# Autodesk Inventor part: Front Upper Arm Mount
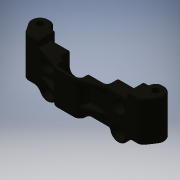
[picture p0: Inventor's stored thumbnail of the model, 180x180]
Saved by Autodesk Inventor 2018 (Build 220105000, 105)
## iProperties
Shininess: 41.0
Compacted: True
Length Units: 11272
Angle Units: 11279
Time Units: 11290
Mass Units: 11286
Length Display Precision: 3
Angle Display Precision: 2
Company: Autodesk
Created: 2001-02
Part Number: Front Upper Arm Mount
Document SubType Name: Modeling
Designer: Autodesk, Inc.
Material: Stiffzel
Project: Inventor Samples
Density: 1.28 g/cm^3
Mass: 8.2438 g
Surface Area: 43.7502 cm^2
Volume: 6.44047 cm^3
Appearance: Stiffzel
Density: 0.0
Volumn: 0.0
Area: 0.0
PropertySet Name: Model Information
Control State: 0
Master: False
Checked Out: False
Author: Autodesk, Inc.
Revision Number: A
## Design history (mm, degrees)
sketch "Sketch1"
  geometry: L1 (20.137, 81.089)-(30.678, 81.089); L2 (30.678, 81.089)-(30.678, 100.139); L3 (30.678, 100.139)-(20.137, 100.139); L4 (20.137, 100.139)-(20.137, 81.089); L5 (-21.011, 81.089)-(-31.552, 81.089); L6 (-31.552, 81.089)-(-31.552, 100.139); L7 (-31.552, 100.139)-(-21.011, 100.139); L8 (-21.011, 100.139)-(-21.011, 81.089)
  constraints: 16 end point, 4 parallel, 3 collinear, 2 horizontal, 2 perpendicular
  dimensions: "d0" = 41.148 distance between parallel lines of L4 L8; "d1" = 10.541 distance of L2.end L3.end; "d2" = 19.05 distance of L1.end L2.end
extrude "Extrusion1" new body sketch "Sketch1" distance "d3" = 8.001; taper "d4" = 0 deg
sketch "Sketch15"
  geometry: L1 (21.011, 81.089)-(31.552, 81.089) reference; L2 (31.552, 100.139)-(23.551, 100.139); L3 (23.551, 100.139)-(23.551, 81.089); L4 (23.551, 81.089)-(31.552, 81.089); L5 (31.552, 81.089)-(31.552, 100.139); L6 (-30.678, 81.089)-(-30.678, 100.139) reference; L7 (-30.678, 100.139)-(-20.137, 100.139) reference; L8 (-30.678, 81.089)-(-20.137, 81.089) reference; L9 (-22.677, 100.139)-(-22.677, 81.089)
  constraints: 10 end point, 3 point on line, 2 parallel, 2 perpendicular, 1 horizontal
  dimensions: "d81" = 8.001 distance between parallel lines of L5 L3 (= d3); "d82" = 8.001 distance between parallel lines of L9 L6 (= d3)
extrude "Extrusion12" join sketch "Sketch15" distance "d83" = 3.175; taper "d84" = 0 deg
fillet "Fillet1" dims "d5" = 4.0005 (= 0.5 x d3)
sketch "Sketch16"
  geometry: L1 (0, 0)-(0, 7.176) reference; L2 (0, 0)-(10.541, 0) reference; L3 (8.001, 11.176)-(4.001, 11.176) reference; L4 (62.23, 7.176)-(62.23, 0) reference; L5 (51.689, 0)-(62.23, 0) reference; L6 (0.679, 4.945)-(4.001, 0); L7 (61.551, 4.945)-(58.229, 0); A1 r 4.001 centre (4.001, 7.176) between (4.001, 11.176) and (0, 7.176) reference; A2 r 4.001 centre (58.229, 7.176) between (62.23, 7.176) and (58.229, 11.176) reference; A3 r 4.001 centre (58.229, 7.176) between (61.551, 4.945) and (62.23, 7.176); A4 r 4.001 centre (4.001, 7.176) between (4.001, 11.176) and (0.679, 4.945); 1 further point
  constraints: 6 point on circle, 5 end point, 3 coincident, 2 centre point, 2 point on line, 2 tangent, 2 vertical alignment
extrude "Extrusion13" cut sketch "Sketch16" extent not by distance; stored distance "d85" = 2.54; taper "d86" = 0 deg
sketch "Sketch2"
  geometry: L1 (-21.011, 100.139)-(-21.011, 81.089) reference; L2 (20.137, 81.089)-(20.137, 100.139) reference; L3 (20.137, 81.089)-(-21.011, 81.089); L4 (-21.011, 81.089)-(-21.011, 97.281); L5 (-21.011, 97.281)-(20.137, 97.281); L6 (20.137, 97.281)-(20.137, 81.089)
  constraints: 8 end point, 2 parallel, 1 horizontal, 1 perpendicular, 1 point on line
  dimensions: "d6" = 16.1925 distance between parallel lines of L3 L5
extrude "Extrusion2" join sketch "Sketch2" distance "d7" = 6.35; taper "d8" = 0 deg
sketch "Sketch3"
  geometry: L1 (20.137, 97.281)-(20.137, 100.139) reference; L2 (-21.011, 100.139)-(-21.011, 97.281) reference; L3 (26.677, 81.089)-(-27.552, 81.089) reference; C1 r 4.001 at (16.136, 81.089); C2 r 4.001 at (-17.011, 81.089)
  constraints: 2 centre point, 2 point on line, 2 tangent, 1 equal radius
  dimensions: "d9" = 8.001 diameter of C1
extrude "Extrusion3" join sketch "Sketch3" distance "d10" = 6.35 (= d7); taper "d11" = 0 deg
fillet "Fillet2" dims "d12" = 3.175
sketch "Sketch4"
  geometry: L1 (41.148, 6.35)-(0, 6.35) reference; L2 (41.148, 0)-(0, 0) reference; L3 (41.148, 6.35)-(41.148, 0) reference; L4 (23.559, 0)-(23.559, -1.016); L5 (20.384, -4.191)-(12.764, -4.191); L6 (9.589, -1.016)-(9.588, 0); L7 (8.001, 0)-(8.001, 6.35) reference; A1 r 3.175 centre (20.384, -1.016) between (20.384, -4.191) and (23.559, -1.016); A2 r 3.175 centre (12.764, -1.016) between (9.589, -1.016) and (12.764, -4.191)
  constraints: 6 end point, 4 point on circle, 4 tangent, 2 centre point, 2 perpendicular, 2 point on line, 1 equal radius, 1 parallel
  dimensions: "d13" = 3.175 radius of A1; "d14" = 10.541 distance between parallel lines of L1 L5; "d15" = 13.97 distance between parallel lines of L6 L4; "d17" = 1.5875 distance between parallel lines of L7 L6
extrude "Extrusion4" join sketch "Sketch4" stored distance "d18" = 25.4; taper "d19" = 0 deg
sketch "Sketch5"
  geometry: L1 (9.588, -6.35)-(0, -6.35) reference; L2 (9.588, -6.35)-(9.589, -7.366) reference; L3 (23.559, -7.366)-(23.559, -6.35) reference; L4 (41.148, -6.35)-(23.559, -6.35) reference; L5 (11.668, -10.346)-(0.794, -6.35); L6 (21.479, -10.346)-(32.353, -6.35); A1 r 3.175 centre (12.764, -7.366) between (9.589, -7.366) and (12.764, -10.541) reference; A2 r 3.175 centre (20.384, -7.366) between (20.384, -10.541) and (23.559, -7.366) reference
  constraints: 4 end point, 2 point on circle, 2 tangent, 1 midpoint, 1 point on line
  dimensions: "d20" = 10.87462 horizontal distance of L6.start L6.end (derived); "d21" = 10.87462 horizontal distance of L5.start L5.end (= d20)
extrude "Extrusion5" join sketch "Sketch5" distance "d22" = 2.54; taper "d23" = 0 deg
sketch "Sketch6"
  geometry: L1 (41.148, 0)-(0, 0) reference; L2 (12.764, -10.541)-(20.384, -10.541) reference; L3 (9.588, -6.35)-(9.589, -7.366) reference; L4 (12.764, -10.541)-(20.384, -10.541) reference; L5 (23.559, -7.366)-(23.559, -6.35) reference; L6 (21.971, 0)-(21.971, -7.366); L7 (20.384, -8.954)-(12.764, -8.954); L8 (11.176, -7.366)-(11.176, 0); A1 r 3.175 centre (12.764, -7.366) between (9.589, -7.366) and (12.764, -10.541) reference; A2 r 3.175 centre (20.384, -7.366) between (20.384, -10.541) and (23.559, -7.366) reference; A3 r 1.587 centre (20.384, -7.366) between (20.384, -8.954) and (21.971, -7.366); A4 r 1.588 centre (12.764, -7.366) between (11.176, -7.366) and (12.764, -8.954)
  constraints: 6 end point, 4 point on circle, 4 tangent, 2 centre point, 2 concentric, 2 parallel, 2 point on line, 1 perpendicular
  dimensions: "d24" = 1.5875 distance between parallel lines of L2 L7
extrude "Extrusion6" cut sketch "Sketch6" extent not by distance; stored distance "d25" = 2.54; taper "d26" = 0 deg
pattern_linear "Rectangular Pattern1" dims "d29" = 10.541
fillet "Fillet21" dims "d87" = 3.175
fillet "Fillet4" dims "d31" = 0.381
fillet "Fillet5" dims "d32" = 0.8128
sketch "Sketch7"
  geometry: C1 r 2.921 at (-17.011, 81.089); A1 r 4.001 centre (-17.011, 81.089) between (-20.598, 79.319) and (-13.01, 81.089) reference
  constraints: 1 centre point, 1 coincident
  dimensions: "d33" = 5.842 diameter of C1
extrude "Extrusion7" cut sketch "Sketch7" distance "d34" = 3.81; taper "d35" = 0 deg
sketch "Sketch8"
  geometry: C1 r 2.921 at (16.136, 81.089); A1 r 4.001 centre (16.136, 81.089) between (12.136, 81.089) and (19.724, 79.319) reference
  constraints: 1 centre point, 1 coincident
  dimensions: "d36" = 5.842 diameter of C1
extrude "Extrusion8" cut sketch "Sketch8" distance "d37" = 3.81 (= d34); taper "d38" = 0 deg
fillet "Fillet6" dims "d39" = 0.8128
fillet "Fillet8" dims "d41" = 0.8128
fillet "Fillet9" dims "d42" = 0.8128
fillet "Fillet22" dims "d88" = 3.175
fillet "Fillet10" dims "d43" = 0.8128
fillet "Fillet11" dims "d44" = 0.762
fillet "Fillet12" dims "d45" = 0.7874
fillet "Fillet13" dims "d46" = 0.7874
fillet "Fillet14" dims "d47" = 0.7874
fillet "Fillet15" dims "d48" = 0.7874
workplane "Work Plane1"
sketch "Sketch9"
  geometry: L1 (9.569, -3.746)-(0.532, -3.746); L2 (0, -0.825)-(7.62, -0.826) reference
  constraints: 2 end point, 1 horizontal
  dimensions: "d50" = 2.921 distance between parallel lines of L2 L1
feature "Rib1" sketch "Sketch9" dims "d51" = 2.54, "d52" = 2.54
fillet "Fillet16" dims "d53" = 0.7874
fillet "Fillet17" dims "d54" = 0.7874
pattern_linear "Rectangular Pattern2" dims "d57" = 11.049
sketch "Sketch10"
  geometry: C1 r 2.921 at (0, 0) reference
extrude "Extrusion9" cut sketch "Sketch10" extent not by distance; stored distance "d58" = 3.81 (= d34); taper "d59" = 0 deg
fillet "Fillet18" dims "d60" = 0.381
sketch "Sketch11"
  geometry: C1 r 2.921 at (0, 0) reference; C2 r 2.921 at (33.147, 0) reference; C3 r 2.921 at (33.147, -11.049) reference; C4 r 2.921 at (0, -11.049) reference; 4 further points
  constraints: 4 coincident
hole "Hole1" sketch "Sketch11" at (0, -11.049), (33.147, 0), (33.147, -11.049), (0, 0) diameter "d61" = 3.175; stored, may be unused: countersink angle "d65" = 60 deg, drill point angle "d67" = 118 deg; dims "d62" = 12.7, "d63" = 9.525, "d64" = 6.35, "d66" = 19.05
sketch "Sketch12"
  geometry: 8 further points
  constraints: 2 coincident, 2 other
hole "Hole2" sketch "Sketch12" at (5.728, -0.063), (-48.501, -0.064) diameter "d68" = 3.175; stored, may be unused: countersink angle "d72" = 60 deg, drill point angle "d74" = 118 deg; dims "d69" = 12.7, "d70" = 9.525, "d71" = 6.35, "d73" = 19.05
workaxis "Work Axis1"
sketch "Sketch13"
  geometry: C1 r 17.399 at (-12.529, 4.432); 1 further point
  constraints: 1 centre point, 1 coincident
extrude "Extrusion10" cut sketch "Sketch13" distance "d75" = 8.89; taper "d76" = 0 deg
sketch "Sketch14"
  geometry: C1 r 17.399 at (19.082, 4.432); A1 r 17.399 centre (19.082, 4.432) between (2.064, 0.813) and (7.366, -8.431) reference; 1 further point
  constraints: 1 centre point, 1 coincident, 1 concentric
extrude "Extrusion11" cut sketch "Sketch14" distance "d79" = 2.54; taper "d80" = 0 deg
fillet "Fillet19" dims "d77" = 1.5875
fillet "Fillet20" dims "d78" = 0.8128
fillet "Fillet23" dims "d89" = 0.762 (derived)
body "Solid1"
other parameters: "d49" = -3.175, "d90" = 0, "d91" = 0, "d92" = 0, "d93" = 0
